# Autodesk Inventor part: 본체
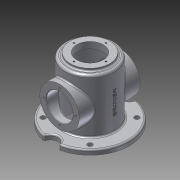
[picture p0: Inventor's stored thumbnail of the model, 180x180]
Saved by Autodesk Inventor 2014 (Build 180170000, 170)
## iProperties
Created: 2018-04
Part Number: 본체
Material: 알루미늄 6061
Document SubType Name: Modeling
Designer: kb542
Density: 2.71 g/cm^3
Appearance: 알루미늄 - 평지
Mass: 1151.53 g
Surface Area: 1201.34 cm^2
Volume: 424.919 cm^3
Author: kb542
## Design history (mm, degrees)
sketch "스케치1"
  geometry: L1 (0, 0)-(0, 133); L2 (27, 133)-(40, 133); L3 (40, 133)-(40, 128); L4 (40, 128)-(50, 128); L5 (50, 128)-(50, 18); L6 (50, 18)-(80, 18); L7 (80, 18)-(80, 8); L8 (80, 8)-(50, 8); L9 (50, 8)-(50, 0); L10 (50, 0)-(45, 0); L11 (45, 0)-(45, 120); L12 (45, 120)-(27, 120); L13 (27, 120)-(27, 133)
  constraints: 26 end point, 10 parallel, 2 horizontal alignment, 2 perpendicular, 1 vertical, 1 vertical alignment
  dimensions: "d0" = 133 distance of L1.start L1.end; "d1" = 8 distance between parallel lines of L10 L8; "d2" = 13 distance between parallel lines of L12 L2; "d3" = 10 distance between parallel lines of L8 L6; "d4" = 54 diameter of L13 L1; "d5" = 80 diameter of L3 L1; "d6" = 110 distance between parallel lines of L6 L4; "d7" = 90 diameter of L11 L1; "d8" = 100 diameter of L9 L1; "d10" = 160 diameter of L7 L1
revolve "회전1" sketch "스케치1" stored, may be unused: angle "d9" = 90 deg
node "작업 평면1"
sketch "스케치2"
  geometry: L1 (-50, 0)-(50, 0) reference; L2 (-80, 8)-(80, 8) reference; C1 r 27 at (0, 68); C2 r 40 at (0, 68); 1 further point
  constraints: 2 centre point, 1 coincident, 1 vertical alignment
  dimensions: "d13" = 80 diameter of C2; "d14" = 54 diameter of C1; "d45" = 60 distance from line of L2 C1.centre
extrude "돌출1" join sketch "스케치2" stored distance "d15" = 10; taper "d16" = 0 deg
extrude "돌출2" cut sketch "스케치2" stored distance "d17" = 10; taper "d18" = 0 deg
sketch "스케치5"
  geometry: C1 r 27 at (0, 0) reference; C2 r 40 at (0, 0) reference; A1 r 32.5 centre (0, 0) between (0, 32.5) and (-32.5, 0); 3 further points
  constraints: 4 point on circle, 2 horizontal alignment, 2 vertical alignment, 1 centre point, 1 coincident
  dimensions: "d27" = 65 diameter of A1
hole "구멍1" sketch "스케치5" at (0, 32.5), (-32.5, 0), (32.5, 0), (0, -32.5) diameter "d28" = 3.242; stored, may be unused: countersink angle "d32" = 90 deg, drill point angle "d34" = 118 deg; dims "d29" = 8, "d30" = 4, "d31" = 2, "d33" = 10
sketch "스케치6"
  geometry: C1 r 40 at (0, 0) reference; C2 r 27 at (0, 0) reference; A1 r 32.5 centre (0, 0) between (0, 32.5) and (-32.5, 0); 2 further points
  constraints: 4 point on circle, 2 horizontal alignment, 2 vertical alignment, 1 centre point, 1 coincident
  dimensions: "d35" = 65 diameter of A1
hole "구멍2" sketch "스케치6" at (0, 32.5), (-32.5, 0), (0, -32.5), (32.5, 0) diameter "d36" = 3.242; stored, may be unused: countersink angle "d40" = 90 deg, drill point angle "d42" = 118 deg; dims "d37" = 8, "d38" = 4, "d39" = 2, "d41" = 10
node "작업 평면2"
sketch "스케치3"
  geometry: 2 further points
  constraints: 1 horizontal alignment, 1 other
  dimensions: "d19" = 70 distance of point (-73, 0) point (-3, 0)
feature "엠보싱1" sketch "스케치3" dims "d20" = 0.5, "d21" = 0
sketch "스케치4"
  geometry: L1 (0, 0)-(67.5, 0); L2 (0, 0)-(47.73, 47.73); C1 r 15 at (0, 80); C2 r 15 at (0, -80); C3 r 5 at (47.73, 47.73); C4 r 5 at (-47.73, 47.73); C5 r 5 at (-47.73, -47.73); C6 r 5 at (47.73, -47.73); A1 r 80 centre (0, 0) between (0, 80) and (0, -80); A2 r 67.5 centre (0, 0) between (67.5, 0) and (47.73, 47.73); 1 further point
  constraints: 8 centre point, 4 end point, 4 point on circle, 3 coincident, 2 vertical alignment, 1 equal radius, 1 horizontal, 9 other
  dimensions: "d23" = 30 diameter of C1; "d24" = 160 diameter of A1; "d46" = 135 diameter of A2; "d47" = 45 deg angle of L1 L2; "d48" = 10 diameter of C3; "d51" = 360 deg dimension on L1.start C3.centre (derived)
extrude "돌출3" cut sketch "스케치4" stored distance "d25" = 11; taper "d26" = 0 deg
fillet "모깎기1" dims "d22" = 5, "d43" = 3
fillet "모깎기2" dims "d44" = 3
chamfer "모따기1" distance "d53" = 1; stored, may be unused: second distance "d54" = 2, angle "d55" = 45 deg
node "솔리드1"
mirror "대칭1"
other parameters: "d11" = 62
